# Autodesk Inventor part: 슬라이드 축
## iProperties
Created: 2012-05
Part Number: 슬라이드 축
Document SubType Name: 모델링
Designer: SeoGD™
Mass: 19.8501 g
Surface Area: 63.0734 cm^2
Volume: 19.8501 cm^3
Density: 1 g/cm^3
변환 표준: STEP AP214IS
파일 이름: C:\Users\SeoGD\Desktop\?쒗뿕\異?stp
전처리기: Build: 253, Release: 2010 SP1 - Date: Wed 07/29/2009
전송 단위: 밀리미터
불확실성: 0.01
Author: SeoGD™
